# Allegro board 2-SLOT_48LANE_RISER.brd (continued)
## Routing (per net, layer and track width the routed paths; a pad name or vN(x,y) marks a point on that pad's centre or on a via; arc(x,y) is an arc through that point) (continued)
85OHM_BOT_10INCH_DP: length 254
  BOTTOM w0.135: U45.1 -15.06,45.46 -15.06,43.23 -15.27,42.02 -15.02,41.66 -7.7,40.37 -7.55,40.15 -7.64,39.63 -7.85,39.48 -17.46,41.18 -17.9,40.88 -18.03,40.1 -17.76,39.7 -7.93,37.97 -7.73,37.69 -7.81,37.23 -8.03,37.07 -17.33,38.71 -17.72,38.45 -17.88,37.62 -17.61,37.23 -8.13,35.56 -7.99,35.35 -8.07,34.87 -8.34,34.69 -17.4,36.28 -17.75,36.04 -17.9,35.21 -17.61,34.79 -8.1,33.12 -7.97,32.93 -8.07,32.36 -8.25,32.23 -17.39,33.84 -17.77,33.58 -17.92,32.72 -17.67,32.36 -8.15,30.68 -8.01,30.48 -8.1,29.93 -8.3,29.8 -17.46,31.41 -17.85,31.14 -18,30.3 -17.73,29.93 -8.18,28.25 -8.05,28.05 -8.15,27.48 -8.32,27.36 -17.33,28.95 -17.7,28.69 -17.72,28.57 -17.84,27.87 -17.56,27.48 -8.41,25.84 -8.3,25.69 -8.4,25.12 -8.61,24.97 -17.45,26.53 -17.85,26.21 -17.95,25.43 -17.67,25.03 -8.32,23.39 -8.21,23.23 -8.32,22.64 -8.51,22.51 -17.52,24.1 -17.9,23.84 -17.92,23.71 -18.03,23.05 -17.73,22.62 -8.63,21.02 -8.48,20.73 -8.57,20.26 -8.78,20.12 -17.17,21.6 -17.56,21.33 -17.7,20.51 -17.42,20.11 -8.72,18.57 -8.57,18.36 -8.67,17.8 -8.84,17.68 -17.33,19.18 -17.71,18.91 -17.86,18.07 -17.6,17.7 -8.67,16.12 -8.57,15.98 -8.68,15.34 -8.83,15.24 -17.08,16.7 -17.51,16.4 -17.64,15.67 -17.32,15.21 -10.17,13.95 -10.05,13.78 -10.16,13.14 -10.29,13.06 -13.48,13.62 -14.35,13.46 -14.94,12.62 -14.94,9.77 U43.2
85OHM_L2_5INCH_DN: length 127
  TOP w0.135: U29.2 -7.39,257.76 -7.39,258.17 v2(-7.16,258.4) ; U25.1 -7.39,279.02 -7.39,278.61 v2(-7.16,278.38)
  IN2 w0.145: v2(-7.16,278.38) -7.4,278.14 -7.4,276.39 -6.9,275.67 -5.04,275.34 -4.69,274.85 -4.8,274.25 -5.3,273.9 -12.66,275.2 -12.82,275.08 -12.93,274.47 -12.81,274.31 -5.45,273.01 -5.1,272.51 -5.21,271.91 -5.71,271.56 -13.2,272.88 -13.37,272.77 -13.48,272.16 -13.36,271.99 -5.87,270.67 -5.52,270.17 -5.62,269.57 -6.12,269.22 -13.71,270.56 -13.88,270.45 -13.99,269.84 -13.87,269.67 -6.28,268.33 -5.93,267.83 -6.04,267.23 -6.53,266.89 -14.58,268.31 -14.75,268.19 -14.85,267.58 -14.74,267.41 -6.69,265.99 -6.34,265.5 -6.45,264.9 -6.95,264.55 -16.13,266.17 -16.44,265.95 -16.51,265.58 -16.29,265.28 -7.1,263.66 -6.75,263.16 -6.86,262.56 -7.36,262.21 -16.55,263.83 -16.85,263.62 -16.92,263.25 -16.7,262.94 -7.52,261.32 -7.17,260.82 -7.4,259.49 -7.4,258.64 v2(-7.16,258.4)
85OHM_L2_5INCH_DP: length 127
  TOP w0.135: v2(-7.92,258.4) -7.69,258.17 -7.69,257.77 U29.1 ; v2(-7.92,278.38) -7.69,278.62 -7.69,279.02 U25.2
  IN2 w0.145: v2(-7.92,258.4) -7.68,258.64 -7.68,259.51 -7.46,260.75 -7.68,261.06 -16.87,262.68 -17.21,263.18 -17.11,263.78 -16.61,264.13 -7.42,262.51 -7.12,262.72 -7.05,263.09 -7.27,263.4 -16.45,265.02 -16.8,265.52 -16.7,266.12 -16.2,266.46 -7.01,264.84 -6.7,265.06 -6.64,265.43 -6.85,265.74 -14.9,267.16 -15.15,267.51 -15,268.35 -14.64,268.6 -6.6,267.18 -6.29,267.4 -6.23,267.77 -6.44,268.08 -14.03,269.41 -14.28,269.77 -14.13,270.61 -13.78,270.86 -6.19,269.52 -5.88,269.73 -5.81,270.11 -6.03,270.41 -13.53,271.74 -13.78,272.09 -13.63,272.93 -13.27,273.18 -5.77,271.86 -5.47,272.07 -5.4,272.44 -5.62,272.75 -12.98,274.05 -13.23,274.41 -13.08,275.24 -12.72,275.49 -5.36,274.2 -5.05,274.41 -4.99,274.78 -5.2,275.09 -7.04,275.41 -7.06,275.42 -7.68,276.3 -7.68,278.14 v2(-7.92,278.38)
85OHM_L2_10INCH_DN: length 254
  TOP w0.135: v2(-8.18,72.01) -7.95,71.78 -7.95,71.37 U33.1 ; v2(-8.18,106.43) -7.94,106.66 -7.94,107.06 U37.2
  IN2 w0.145: v2(-8.18,106.43) -7.94,106.18 -7.94,104.78 -7.79,103.98 -6.64,102.33 -6.77,101.6 -6.93,101.48 -12.68,102.49 -13.16,102.15 -13.27,101.53 -12.94,101.05 -4.14,99.5 -4.02,99.33 -4.13,98.72 -4.3,98.6 -13.09,100.15 -13.59,99.8 -13.7,99.21 -13.35,98.71 -4.56,97.16 -4.45,96.99 -4.55,96.38 -4.72,96.27 -13.51,97.82 -14,97.47 -14.11,96.87 -13.76,96.37 -4.86,94.8 -4.75,94.64 -4.85,94.03 -5.02,93.91 -13.92,95.48 -14.41,95.13 -14.52,94.53 -14.17,94.03 -5.17,92.45 -5.06,92.28 -5.16,91.67 -5.33,91.55 -14.33,93.14 -14.83,92.79 -14.93,92.19 -14.58,91.7 -4.58,89.93 -4.46,89.76 -4.57,89.16 -4.73,89.04 -14.74,90.8 -15.24,90.45 -15.34,89.86 -15,89.36 -4.97,87.59 -4.82,87.38 -4.92,86.81 -5.09,86.69 -15.15,88.46 -15.65,88.12 -15.76,87.52 -15.41,87.02 -5.29,85.24 -5.12,85 -5.22,84.45 -5.39,84.33 -15.57,86.13 -16.06,85.78 -16.17,85.18 -15.82,84.68 -5.6,82.88 -5.44,82.65 -5.53,82.17 -5.78,81.99 -15.98,83.79 -16.48,83.44 -16.58,82.84 -16.23,82.34 -5.8,80.51 -5.65,80.29 -5.75,79.74 -5.94,79.61 -16.39,81.45 -16.89,81.1 -16.99,80.5 -16.65,80.01 -6.44,78.21 -6.27,77.96 -6.35,77.52 -6.63,77.32 -16.8,79.11 -17.3,78.76 -17.41,78.17 -17.06,77.67 -7.72,76.02 -7.48,75.68 -7.92,73.19 -7.92,72.26 v2(-8.18,72.01)
85OHM_L2_10INCH_DP: length 254
  TOP w0.135: U33.2 -7.65,71.37 -7.65,71.78 v2(-7.42,72.01) ; U37.1 -7.64,107.06 -7.64,106.65 v2(-7.42,106.43)
  IN2 w0.145: v2(-7.42,72.01) -7.64,72.24 -7.64,73.17 -7.19,75.75 -7.56,76.28 -16.9,77.92 -17.11,78.23 -17.05,78.6 -16.74,78.82 -6.56,77.02 -6.09,77.35 -5.97,78.03 -6.28,78.46 -16.48,80.26 -16.7,80.57 -16.63,80.94 -16.33,81.16 -5.88,79.31 -5.49,79.58 -5.36,80.36 -5.64,80.76 -16.07,82.6 -16.29,82.91 -16.22,83.28 -15.91,83.49 -5.71,81.69 -5.27,82 -5.15,82.72 -5.44,83.14 -15.66,84.94 -15.87,85.25 -15.81,85.62 -15.5,85.83 -5.32,84.04 -4.97,84.29 -4.83,85.06 -5.13,85.49 -15.25,87.28 -15.46,87.58 -15.4,87.95 -15.09,88.17 -5.03,86.39 -4.67,86.64 -4.53,87.45 -4.81,87.85 -14.83,89.61 -15.05,89.92 -14.98,90.29 -14.68,90.51 -4.67,88.74 -4.31,88.99 -4.16,89.82 -4.29,90 -4.42,90.19 -14.42,91.95 -14.64,92.26 -14.57,92.63 -14.26,92.84 -5.27,91.26 -4.91,91.51 -4.76,92.35 -5.01,92.7 -14.01,94.29 -14.23,94.6 -14.16,94.97 -13.85,95.18 -4.96,93.61 -4.6,93.86 -4.45,94.7 -4.7,95.06 -13.6,96.63 -13.81,96.93 -13.75,97.3 -13.44,97.52 -4.66,95.97 -4.3,96.22 -4.15,97.06 -4.4,97.42 -13.18,98.96 -13.4,99.27 -13.34,99.64 -13.03,99.86 -4.23,98.31 -3.88,98.56 -3.73,99.39 -3.79,99.49 -3.98,99.75 -12.77,101.3 -12.98,101.6 -12.91,101.99 -12.62,102.2 -6.87,101.18 -6.51,101.43 -6.34,102.39 -7.53,104.09 -7.66,104.81 -7.66,106.18 v2(-7.42,106.43)
85OHM_TOP_5INCH_DN: length 127
  TOP w0.135: U26.2 -14.93,340.62 -14.93,338.38 -15.14,337.17 -14.89,336.81 -7.57,335.52 -7.42,335.3 -7.51,334.78 -7.72,334.63 -17.34,336.33 -17.77,336.02 -17.91,335.24 -17.77,335.05 -17.63,334.85 -7.63,333.09 -7.4,332.76 -7.48,332.3 -7.66,332.18 -17.21,333.86 -17.6,333.6 -17.75,332.76 -17.48,332.38 -7.91,330.69 -7.7,330.39 -7.79,329.89 -7.93,329.79 -17.05,331.39 -17.43,331.13 -17.58,330.31 -17.29,329.91 -8.27,328.32 -8.09,328.05 -8.18,327.52 -8.33,327.41 -17.2,328.98 -17.59,328.71 -17.74,327.87 -17.47,327.5 -8.54,325.92 -8.44,325.77 -8.55,325.14 -8.7,325.04 -16.96,326.49 -17.38,326.2 -17.51,325.47 -17.19,325.01 -10.04,323.74 -9.92,323.57 -10.04,322.94 -10.16,322.85 -13.35,323.42 -14.22,323.26 -14.81,322.42 -14.81,319.58 U5.1
85OHM_TOP_5INCH_DP: length 127
  TOP w0.135: U5.2 -14.51,319.58 -14.51,322.33 -14.04,322.98 -13.35,323.11 -10.09,322.53 -9.86,322.69 -9.76,322.76 -9.6,323.65 -9.87,324.02 -17.01,325.28 -17.19,325.54 -17.1,326.02 -16.89,326.17 -8.63,324.72 -8.27,324.96 -8.12,325.85 -8.37,326.2 -17.3,327.78 -17.41,327.94 -17.31,328.53 -17.13,328.66 -8.26,327.09 -7.9,327.34 -7.77,328.13 -8.09,328.59 -17.12,330.19 -17.25,330.38 -17.2,330.66 -17.15,330.95 -16.98,331.07 -7.86,329.46 -7.69,329.59 -7.68,329.59 -7.51,329.71 -7.38,330.46 -7.56,330.72 -7.74,330.97 -17.31,332.66 -17.43,332.83 -17.37,333.13 -17.32,333.42 -17.14,333.54 -7.58,331.86 -7.2,332.12 -7.08,332.83 -7.45,333.36 -17.45,335.13 -17.59,335.32 -17.49,335.85 -17.27,336 -7.65,334.31 -7.23,334.61 -7.1,335.37 -7.39,335.79 -14.71,337.09 -14.82,337.24 -14.63,338.35 -14.63,340.62 U26.1
85OHM_TOP_10INCH_DN: length 254
  TOP w0.135: U34.2 -14.93,164.85 -14.93,162.61 -15.14,161.4 -14.89,161.04 -7.57,159.75 -7.42,159.53 -7.51,159.01 -7.72,158.86 -17.34,160.56 -17.77,160.26 -17.91,159.48 -17.63,159.08 -7.8,157.35 -7.6,157.07 -7.68,156.61 -7.9,156.45 -17.21,158.09 -17.6,157.83 -17.75,157 -17.48,156.61 -8.01,154.94 -7.86,154.73 -7.95,154.25 -8.21,154.07 -17.27,155.66 -17.63,155.42 -17.77,154.59 -17.48,154.17 -7.98,152.5 -7.84,152.31 -7.94,151.74 -8.12,151.61 -17.27,153.22 -17.64,152.96 -17.79,152.1 -17.54,151.74 -8.02,150.06 -7.88,149.86 -7.98,149.31 -8.17,149.18 -17.33,150.79 -17.72,150.52 -17.87,149.68 -17.61,149.31 -8.06,147.63 -7.92,147.43 -8.02,146.86 -8.2,146.74 -17.2,148.33 -17.57,148.07 -17.59,147.95 -17.71,147.25 -17.44,146.86 -8.28,145.22 -8.17,145.07 -8.27,144.5 -8.49,144.35 -17.32,145.91 -17.72,145.59 -17.83,144.81 -17.54,144.41 -8.2,142.77 -8.09,142.61 -8.19,142.02 -8.38,141.89 -17.39,143.48 -17.77,143.22 -17.79,143.09 -17.91,142.43 -17.6,142 -8.5,140.4 -8.36,140.11 -8.44,139.64 -8.65,139.5 -17.05,140.98 -17.43,140.71 -17.58,139.89 -17.29,139.49 -8.59,137.95 -8.44,137.74 -8.54,137.18 -8.71,137.06 -17.2,138.56 -17.59,138.29 -17.74,137.45 -17.47,137.08 -8.54,135.5 -8.44,135.36 -8.55,134.72 -8.7,134.62 -16.96,136.08 -17.38,135.78 -17.51,135.05 -17.19,134.59 -10.04,133.33 -9.92,133.16 -10.04,132.52 -10.16,132.44 -13.35,133 -14.22,132.84 -14.81,132 -14.81,129.16 U30.1
85OHM_TOP_10INCH_DP: length 254
  TOP w0.135: U34.1 -14.63,164.85 -14.63,162.58 -14.82,161.47 -14.71,161.32 -7.39,160.03 -7.1,159.6 -7.23,158.84 -7.65,158.54 -17.27,160.24 -17.49,160.08 -17.59,159.55 -17.45,159.36 -7.62,157.63 -7.28,157.14 -7.41,156.43 -7.83,156.13 -17.14,157.77 -17.32,157.65 -17.43,157.07 -17.31,156.89 -7.83,155.22 -7.54,154.81 -7.67,154.07 -8.14,153.74 -17.2,155.34 -17.35,155.24 -17.45,154.66 -17.3,154.45 -7.8,152.77 -7.52,152.38 -7.66,151.56 -8.05,151.29 -17.19,152.9 -17.36,152.78 -17.47,152.17 -17.37,152.02 -7.84,150.34 -7.56,149.93 -7.7,149.13 -8.1,148.85 -17.26,150.47 -17.45,150.34 -17.55,149.76 -17.43,149.59 -7.88,147.9 -7.6,147.5 -7.75,146.68 -8.13,146.42 -17.13,148.01 -17.29,147.89 -17.39,147.32 -17.26,147.13 -8.11,145.5 -7.85,145.14 -7.99,144.32 -8.42,144.03 -17.24,145.58 -17.44,145.42 -17.51,144.89 -17.37,144.69 -8.02,143.05 -7.76,142.68 -7.91,141.84 -8.31,141.57 -17.32,143.15 -17.49,143.04 -17.58,142.51 -17.43,142.28 -8.29,140.67 -8.04,140.16 -8.16,139.47 -8.58,139.17 -16.98,140.65 -17.15,140.53 -17.25,139.96 -17.12,139.77 -8.42,138.23 -8.12,137.81 -8.26,137.01 -8.64,136.74 -17.13,138.24 -17.31,138.11 -17.41,137.52 -17.3,137.36 -8.37,135.78 -8.12,135.43 -8.27,134.54 -8.63,134.3 -16.89,135.75 -17.1,135.6 -17.19,135.12 -17.01,134.87 -9.87,133.6 -9.6,133.23 -9.76,132.35 -9.86,132.27 -9.86,132.27 -10.09,132.11 -13.35,132.69 -14.04,132.57 -14.51,131.91 -14.51,129.16 U30.2
AT24C64_A0: length 4.7
  TOP w0.114: R281.2 v2(315.16,44.78) R282.1 315.65,43.61 315.65,42.11 315.16,41.63 U7.1
AT24C64_A1: length 4.7
  TOP w0.114: 313.89,41.12 313.89,41.88 314.34,42.32 314.34,43.64 R284.1 v2(313.89,44.78) R283.2
AT24C64_A2: length 4.7
  TOP w0.114: R285.2 v2(312.62,44.78) R286.1 313.13,43.58 313.13,42.29 312.62,41.78 U7.3
AT24C64_WP: length 4.5
  TOP w0.114: R293.2 R294.1 314.56,33.53 314.56,34.52 v2(314.53,34.54) 313.89,35.18 313.89,35.84
CLK_100M_CPU1_PE_FG_DN: length 77.7
  TOP w0.135: v2(282.22,11.99) 282.53,11.68 282.53,10.46 280.87,8.81 280.87,6.83 281.17,6.53 281.17,6.15 280.83,5.8 J5.A14 ; 301.31,56.32 U9.7 301.31,55.38 302.9,53.8 v8(302.9,50.09) 302.9,49.02 v2(303.15,48.77)
  IN2 w0.145: v2(303.15,48.77) 303.13,48.77 302.9,48.54 302.9,45.91 303.4,45.4 303.4,39.62 304.65,38.38 304.65,32.72 304.12,32.18 304.12,30.99 304.42,30.68 304.42,29.49 304.65,29.26 304.65,22.63 303.35,21.34 303.35,14.99 298.38,10.01 283.87,10.01 282.54,11.34 282.54,11.67 v2(282.22,11.99)
CLK_100M_CPU1_PE_FG_DP: length 77.6
  TOP w0.135: v2(302.34,48.77) 302.39,48.77 302.59,48.97 v8(302.59,51.64) 302.59,53.67 301.01,55.26 301.01,55.64 300.91,55.73 U9.6 300.91,56.32 ; J5.A13 281.83,5.8 281.48,6.15 281.48,6.66 281.18,6.96 281.18,8.69 282.83,10.34 282.83,11.79 v2(283.03,11.99)
  IN2 w0.145: v2(283.03,11.99) 282.82,11.77 282.82,11.46 283.99,10.29 285.15,10.29 285.26,10.4 285.89,10.4 286,10.29 289.36,10.29 289.48,10.4 290.1,10.4 290.22,10.29 291.08,10.29 291.19,10.4 291.82,10.4 291.93,10.29 298.26,10.29 298.76,10.79 298.76,10.95 299.2,11.39 299.36,11.39 300.72,12.75 300.72,12.91 301.17,13.36 301.33,13.36 301.94,13.96 301.94,14.12 302.38,14.57 302.54,14.57 303.07,15.1 303.07,21.45 304.37,22.75 304.37,29.14 304.14,29.37 304.14,30.57 303.84,30.87 303.84,32.3 304.37,32.83 304.37,34.3 304.26,34.41 304.26,35.04 304.37,35.15 304.37,36.01 304.26,36.12 304.26,36.75 304.37,36.87 304.37,38.26 303.13,39.51 303.13,39.93 303.02,40.03 303.02,40.69 303.13,40.79 303.13,45.29 302.62,45.8 302.62,48.51 302.36,48.77 v2(302.34,48.77)
CLK_100M_PEX8796_DN: length 3.8
  TOP w0.135: 301.31,61.07 U9.24 301.31,61.59 301.36,61.64 301.36,62.39 301.95,62.98 301.95,64.12 R127.1
CLK_100M_PEX8796_DP: length 3.8
  TOP w0.135: 301.71,61.07 U9.23 301.71,61.58 301.66,61.63 301.66,62.26 302.26,62.86 302.26,64.17 R126.1
CLK_100M_PEX8796_R_DN: length 236.6
  TOP w0.135: R127.2 301.96,65.69 301.96,66.73 301.68,67.01 301.53,67.01 301.09,67.44 301.09,67.59 300.81,67.87 297.92,67.87 297.18,67.13 v8(297.18,66.8) 297.18,64.44 295.31,62.57 295.31,62.47 295.31,62.37 295,62.06 294.9,62.06 294.8,62.06 292.3,59.56 292.3,59.46 292.3,59.46 292.3,59.36 291.99,59.05 291.89,59.05 291.89,59.05 291.79,59.05 289.63,56.89 289.63,56.78 289.63,56.68 289.32,56.37 289.22,56.37 289.21,56.37 289.11,56.37 285.24,52.5 285.24,52.27 284.86,51.89 284.63,51.89 284.25,51.51 284.25,51.28 283.87,50.9 283.64,50.9 281.76,49.02 281.76,48.88 281.76,48.88 281.76,48.74 281.45,48.43 281.31,48.43 281.17,48.43 279.29,46.55 279.29,46.45 279.29,46.45 279.29,46.35 278.98,46.03 278.88,46.03 278.88,46.04 278.78,46.04 277.95,45.21 277.95,44.2 278.11,44.04 278.11,43.5 277.95,43.35 277.95,39.12 276.96,38.13 276.96,34.82 275.95,33.81 275.95,30.56 v2(276.2,30.3)
  IN2 w0.145: v5(125.69,77.96) 125.69,78.07 125.54,78.22 125.33,78.22 125.08,77.97 125.08,76.5 125.2,76.38 125.2,75.71 125.08,75.59 125.08,75.01 125.2,74.89 125.2,74.31 125.08,74.19 125.08,72.64 145.65,52.07 181.05,52.07 183.95,49.17 204.27,49.17 208.84,44.6 208.84,34.84 212.69,30.99 272.73,30.99 273.7,31.95 275.3,31.95 275.92,31.33 275.92,30.56 276.18,30.3 v2(276.2,30.3)
  BOTTOM w0.135: U1.W2 v5(125.69,77.96)
CLK_100M_PEX8796_R_DP: length 236.7
  TOP w0.135: R126.2 302.26,65.63 302.26,66.85 300.94,68.17 297.79,68.17 296.88,67.26 v8(296.88,65.07) 296.88,64.57 277.65,45.34 277.65,39.24 276.66,38.25 276.66,34.95 275.64,33.93 275.64,30.56 v2(275.39,30.3)
  IN2 w0.145: v5(125.69,78.76) 125.69,78.62 125.57,78.5 125.21,78.5 124.8,78.09 124.8,72.52 145.53,51.79 180.94,51.79 183.83,48.9 204.15,48.9 208.56,44.49 208.56,34.72 212.57,30.71 272.85,30.71 273.81,31.67 275.19,31.67 275.64,31.22 275.64,30.53 275.41,30.3 v2(275.39,30.3)
  BOTTOM w0.135: U1.W3 v5(125.69,78.76)
CLK_100M_SLOT1_DN: length 3.8
  TOP w0.135: 303.09,58.5 U9.15 303.61,58.5 303.65,58.45 304.49,58.45 305.08,57.86 306.13,57.86 R125.1
CLK_100M_SLOT1_DP: length 3.8
  TOP w0.135: 303.09,58.1 U9.14 303.6,58.1 303.65,58.15 304.36,58.15 304.96,57.55 306.18,57.55 R124.1
CLK_100M_SLOT1_R_DN: length 59.4
  TOP w0.135: R125.2 307.62,57.94 308.69,57.94 310.77,55.86 310.77,54.1 v2(311,53.87)
  BOTTOM w0.135: J1.A14 281.2,34 281.38,34.06 281.51,33.99 281.64,33.86 281.64,32.39 283.03,30.99 296.42,30.99 299.7,34.26 309.55,34.26 310.8,35.51 310.8,53.7 310.97,53.87 v2(311,53.87)
CLK_100M_SLOT1_R_DP: length 59.4
  TOP w0.135: v2(310.19,53.87) 310.47,54.15 310.47,55.73 308.57,57.63 307.72,57.63 R124.2
  BOTTOM w0.135: J1.A13 281.46,34.51 281.52,34.33 281.69,34.25 281.94,33.99 281.94,32.51 282.23,32.23 282.44,32.23 282.73,31.94 282.73,31.73 283.16,31.29 285.15,31.29 285.33,31.47 285.77,31.47 285.95,31.29 289.65,31.29 289.83,31.47 290.27,31.47 290.45,31.29 294.62,31.29 294.8,31.47 295.24,31.47 295.42,31.29 296.29,31.29 298.09,33.09 298.09,33.2 298.09,33.3 298.41,33.61 298.51,33.61 298.61,33.61 299.57,34.57 301.04,34.57 301.2,34.72 301.69,34.72 301.84,34.57 309.43,34.57 310.49,35.64 310.49,48.59 310.29,48.79 310.29,49.23 310.49,49.43 310.49,53.59 310.21,53.87 v2(310.19,53.87)
CLK_100M_SLOT2_DN: length 4
  TOP w0.135: 300.11,61.07 U9.27 300.11,61.54 300.16,61.58 300.16,62.06 299.13,63.08 299.13,64.14 R123.1
CLK_100M_SLOT2_DP: length 4
  TOP w0.135: R122.1 299.44,64.14 299.44,63.21 300.46,62.18 300.46,61.61 300.51,61.57 U9.26 300.51,61.07
CLK_100M_SLOT2_R_DN: length 27.4
  TOP w0.135: R123.2 299.13,65.66 299.13,66.58 v2(298.86,66.85)
  BOTTOM w0.135: J2.A14 281.2,74.64 281.38,74.7 281.51,74.63 281.64,74.5 281.64,73.02 282.64,72.02 282.64,69.23 284.71,67.16 288.64,67.16 288.82,66.98 289.26,66.98 289.44,67.16 292.5,67.16 292.68,66.98 293.12,66.98 293.29,67.16 296.65,67.16 297.18,67.69 298.81,67.69 299.09,67.41 299.09,67.08 v2(298.86,66.85)
CLK_100M_SLOT2_R_DP: length 27.5
  TOP w0.135: v2(299.67,66.86) 299.44,66.62 299.44,65.66 R122.2
  BOTTOM w0.135: v2(299.67,66.86) 299.39,67.14 299.39,67.54 298.93,68 297.06,68 296.52,67.46 284.84,67.46 282.95,69.35 282.95,72.14 281.94,73.15 281.94,74.63 281.69,74.89 281.52,74.97 281.46,75.15 J2.A13
CLK_BUF_CKPWRGD: length 6.8
  TOP w0.114: 299.71,56.32 U9.3 299.71,55.66 299.31,55.26 299.31,53.6 v2(299.37,53.54) 299.31,53.49 R4.2 299.8,51.02 Q4.D
CLK_BUF_HIBW_BYPM_LOBW_N: length 4
  TOP w0.178: 298.79,54.94 298.79,55.14 299.31,55.67 U9.2 299.31,56.32
  TOP w0.254: 298.79,54.94 298.79,53.94 R2.1 R1.2
CPLD_PWRBRK_BUF_N: length 84.3
  TOP w0.114: U19.2 v2(283.54,85.72) ; U8.4 281.42,18.86 R154.1 281.49,19.34 281.64,19.48 282.86,19.48 283.03,19.66 v1(283.03,22.12) 283.03,23.29 280.98,25.35 v2(280.98,25.73) ; v2(283.36,45.49) 283.08,45.21 U20.2
  IN2 w0.147: v2(280.98,25.73) 281.33,26.09 281.33,28.06 284.87,31.6 286.31,31.6 287.73,33.02 287.73,34.19 286.69,35.23 286.69,38.23 284.15,40.77 284.15,44.7 v2(283.36,45.49) 283.36,47.8 286.71,51.15 286.71,60.08 280.57,66.22 280.57,69.01 281.97,70.41 281.97,74.35 282.16,74.82 282.52,75.18 282.78,75.56 282.78,75.95 282.4,76.87 282.4,77.44 283.05,79.01 283.92,79.88 283.92,81.69 282.88,82.73 282.88,85.52 283.08,85.72 v2(283.54,85.72)
CPLD_PWRBRK_N: length 26.3
  TOP w0.114: U8.2 277.07,19.51 v2(277.06,19.51) ; R152.2 v2(263.7,10.82)
  IN2 w0.147: v2(277.06,19.51) 273.86,16.31 269.7,16.31 264.21,10.82 v2(263.7,10.82)
  BOTTOM w0.114: v2(263.7,10.82) 264.83,9.7 J5.B30
CPLD_SLOT1_PWRBRK_N: length 4.2
  TOP w0.114: R221.1 R216.1 R142.2 285.14,43.45 285.39,43.71 285.39,43.76 285.4,43.76 v2(285.4,44.07) 285.4,44.32 285.16,44.56 U20.4
CPLD_SLOT1_PWRBRK_R1_N: length 3.3
  TOP w0.114: J1.B12 283.8,40.72 R216.2
CPLD_SLOT1_PWRBRK_R2_N: length 19.2
  TOP w0.114: R221.2 v2(278.74,42.65)
  IN1 w0.147: v2(278.74,42.65) 267.73,42.65 J1.B30
CPLD_SLOT2_PWRBRK_N: length 3.8
  TOP w0.114: R214.1 v2(283.8,84.71) 283.8,84.84 284.03,85.08 U19.4 ; R214.1 R143.2 ; R214.1 R215.1
CPLD_SLOT2_PWRBRK_R1_N: length 3.2
  TOP w0.114: J2.B12 283.8,81.36 R214.2
CPLD_SLOT2_PWRBRK_R2_N: length 19.1
  TOP w0.114: R215.2 267.6,83.17 J2.B30
DC_PEX8747_AA18: length 0.6
  BOTTOM w0.114: U1.AA18 v5(124.09,91.56)
DC_PEX8747_AA21: length 0.6
  BOTTOM w0.114: U1.AA21 v5(124.89,93.96)
DC_PEX8747_B9: length 0.6
  BOTTOM w0.114: U1.B9 v5(139.29,83.56)
DC_PEX8747_F13: length 0.6
  BOTTOM w0.114: U1.F13 v5(136.89,87.56)
DC_PEX8747_F20: length 0.6
  BOTTOM w0.114: U1.F20 v5(136.89,93.16)
DC_PEX8747_F21: length 0.6
  BOTTOM w0.114: U1.F21 136.49,93.56 v5(136.09,93.96)
DC_PEX8747_N22: length 0.6
  BOTTOM w0.114: U1.N22 v5(130.49,94.76)
DC_PEX8747_Y16: length 0.6
  BOTTOM w0.114: U1.Y16 v5(124.89,89.96)
DC_PEX8747_Y20: length 0.6
  BOTTOM w0.114: U1.Y20 v5(124.89,93.16)
EMC1412_ADDR: length 2.7
  BOTTOM w0.114: R302.2 306.53,81.15 v4(306.24,80.86) 305.8,80.42 U4.4
EMC1412_ALERT: length 4
  BOTTOM w0.114: R301.2 v4(311.99,80.14) 311.92,80.06 311.92,79.19 311.79,79.07 U4.6
EMC1413_ADDR: length 4.7
  TOP w0.114: U10.7 204.9,80.21 v2(206.59,78.52) 206.91,78.21 R137.2
EMC1413_ALERT_N: length 4.4
  TOP w0.114: R141.2 206.99,79.91 v2(206.55,79.91) 205.74,79.91 204.94,80.71 U10.8
I2C_ADDR0: length 7.8
  TOP w0.102: v5(136.89,80.36) 136.5,79.97 135.96,79.97 135.71,79.72 135.71,79.32 135.33,78.95 135.33,76.71 v6(135.56,76.48)
  TOP w0.114: v6(135.56,76.48) 135.33,76.25 135.33,75.88 135.21,75.75 R108.1 R94.2
  BOTTOM w0.114: U1.F5 v5(136.89,80.36)
I2C_MUX_ADD_A0: length 6.7
  TOP w0.114: U2.1 308.04,41.16 308.54,41.66 v2(309.32,41.66) 309.45,41.78 309.45,43.69 309.72,43.96 R84.1 R83.2
I2C_MUX_ADD_A1: length 5.9
  TOP w0.114: R81.2 v2(308.81,44.73) R82.1 308.23,43.38 308.23,41.88 307.39,41.04 U2.2
I2C_MUX_ADD_A2: length 5.7
  TOP w0.114: U2.21 306.09,32.21 v2(306.2,32.11) 306.45,31.85 306.45,31.07 R80.1 R79.2
I2C_MUX_RST_N: length 3.4
  TOP w0.114: R78.2 307.67,42.62 v2(307.37,42.32) 307.34,42.32 306.74,41.72 U2.3
I2C_PCA9548_2N7002_G2_SCL: length 2.1
  TOP w0.254: R160.2 v2(315.7,28.7) 316.24,28.16 Q19.G
I2C_PCA9548_2N7002_G2_SDA: length 1.9
  TOP w0.254: R163.2 v2(311.84,28.7) 312.05,28.49 Q22.G
I2C_PCA9548_2N7002_G_SCL: length 2.2
  TOP w0.114: R161.2 296.26,24.28 v2(296.5,24.51) 297.23,24.51 Q20.G
I2C_PCA9548_2N7002_G_SDA: length 2.2
  TOP w0.114: R191.2 290.17,24.28 v2(290.4,24.51) 291.14,24.51 Q23.G
I2C_PCA9548_SC1_SLOT2_R_SCL: length 3.2
  TOP w0.114: R22.1 303.61,42.06 v2(304.1,41.57) 304.14,41.53 U2.7
I2C_PCA9548_SC1_SLOT2_SCL: length 35.7
  TOP w0.114: R22.2 304.24,44.6 v2(304.24,44.7) R98.2 ; v2(292.22,65.11) Q15.D 291.78,67.24 R226.1
  BOTTOM w0.114: v2(292.22,65.11) 292.1,64.99 292.1,49.45 294.69,46.86 300.64,46.86 302.3,45.2 302.33,45.2 302.82,44.7 v2(304.24,44.7)
I2C_PCA9548_SC3_SLOT1_R_SCL: length 4.6
  TOP w0.114: U2.11 301.54,41.01 301.25,41.3 300.05,41.3 v2(299.82,41.53) 299.67,41.68 R26.1
I2C_PCA9548_SC3_SLOT1_SCL: length 30.1
  TOP w0.114: R102.2 298.4,44.68 v2(298.4,44.32) 298.76,43.96 R26.2 ; Q21.D 294.32,26.8 294.69,27.16 R228.1 295.23,26.98 295.55,26.65 295.55,26.43 295.56,26.43 v2(295.56,26.26)
  IN2 w0.147: v2(298.4,44.32) 298.4,43.64 298.23,43.47 297.43,43.47 297.28,43.32 297.28,43.03 297.43,42.88 298.25,42.88 298.4,42.73 298.4,42.52 297.52,41.64 297.52,32.76 298.53,31.75 298.53,27.56 298.15,27.18 296.47,27.18 v2(295.56,26.26)
I2C_PCA9548_SC5_3V3_PE_SCL: length 336.7
  TOP w0.114: Q20.S v2(297.68,21.1) ; v2(193.27,82.83) 194.41,83.97 194.41,99.96 188.37,106.01 188.37,113.08 189.06,113.78 CON1.2 191.97,113.78 192.89,112.85 196.85,112.85 v2(203.28,106.43) ; U12.7 105.61,45.11 105.95,45.44 107.4,45.44 R234.2 R194.2 107.81,44.05 108.72,44.05 v2(108.74,44.03)
  IN1 w0.147: v2(193.27,82.83) 160.57,82.83 122.11,44.37 109.22,44.37 108.88,44.03 v2(108.74,44.03)
  IN2 w0.147: v2(203.28,106.43) 206.83,102.87 265.38,102.87 277.45,90.81 284.43,90.81 289.89,85.34 289.89,82.68 291.8,80.77 291.8,79.88 292.94,78.74 292.94,75.69 291.92,74.68 291.92,73.08 290.42,71.57 290.42,67.6 289.73,66.91 289.73,47.78 292.51,45 297.35,45 298.17,45.82 301.6,45.82 301.96,45.47 301.96,42.04 301.58,41.66 301.58,39.98 301.96,39.6 301.96,37.19 301.63,36.86 301.63,32.59 302.21,32 302.21,29.72 302.34,29.59 302.34,22.99 300.45,21.1 v2(297.68,21.1)
I2C_PCA9548_SC5_P1V8_SCL: length 191.6
  TOP w0.114: v5(136.89,81.96) 137.3,81.55 139.59,81.55 140.21,80.92 140.21,80.75 140.72,80.24 142.37,80.24 142.9,80.77 173.75,80.77 203.91,50.61 203.91,45.47 v2(204.45,44.93) ; U12.2 105.61,47.22 v2(106.05,46.79)
  IN2 w0.147: v2(106.05,46.79) 106.1,46.74 108.29,46.74 109.56,45.47 130.13,45.47 132.79,48.13 178.72,48.13 181.42,45.44 203.94,45.44 v2(204.45,44.93)
  BOTTOM w0.114: R277.2 105.36,47.47 v2(106.05,46.79) ; U1.F7 v5(136.89,81.96)
I2C_PCA9548_SC5_PE_R_SCL: length 3.6
  TOP w0.114: R28.1 301.83,32.77 v2(302.08,33.02) 302.84,33.78 U2.16
I2C_PCA9548_SC5_PE_SCL: length 226.5
  TOP w0.114: v2(109.97,46.23) 109.61,45.87 R234.1 ; R28.2 301.83,30.56 v2(301.17,29.89) R104.2 302.34,28.72 302.34,27.05 299.88,24.6 Q20.D
  IN2 w0.147: v2(109.97,46.23) 130.38,46.23 132.92,48.77 179.27,48.77 182.2,45.85 204.65,45.85 205.39,45.11 205.39,32.82 217,21.2 277.49,21.2 v2(280.39,24.1)
  BOTTOM w0.114: v2(280.39,24.1) 280.87,23.62 290.37,23.62 294.41,27.66 296.52,27.66 297.35,28.49 298.44,28.49 298.78,28.83 300.1,28.83 v2(301.17,29.89)
I2C_PCA9548_SC6_3V3_CLK_R_SCL: length 7.7
  TOP w0.114: R90.2 v2(305.52,51.64) 305.26,51.89 304.25,51.89 303.9,52.24 303.9,54.17 302.63,55.45 302.47,55.45 302.11,55.8 U9.9 302.11,56.32
I2C_PCA9548_SC6_3V3_CLK_SCL: length 38.2
  TOP w0.114: Q19.S 314.34,28.45 314.55,28.66 R236.2 314.94,29.34 315.47,29.87 v2(315.47,30.36) 315.25,30.57 R193.2 ; R90.1 v2(315.62,49.97)
  BOTTOM w0.114: v2(315.62,49.97) 316.02,49.97 318.85,47.14 318.85,33.67 317.28,32.1 317.28,31.94 317.57,31.65 317.57,31.44 317.37,31.24 317.2,31.24 316.88,31.56 316.74,31.56 315.54,30.36 v2(315.47,30.36)
I2C_PCA9548_SC6_CLK_R_SCL: length 3.6
  TOP w0.114: R30.1 304.14,31.67 304.14,32.69 v2(303.71,33.12) 304.14,33.55 U2.18
I2C_PCA9548_SC6_CLK_SCL: length 205.7
  TOP w0.114: R106.2 303.86,29.74 v2(303.66,29.95) 303.86,30.15 R30.2 ; Q19.D 314.74,25.32 313.51,26.54 313.51,28.32 313.75,28.56 R236.1 313.26,29.83 313.26,30.99 312.37,31.88 v2(312.37,32) 312.62,32.26 R280.2 ; v2(313.66,77.47) 313.79,77.6 314.91,77.6 316.69,79.38 316.69,83.57 311.23,89.03 296.24,89.03 291.42,93.85 219.33,93.85 210.03,84.56 210.03,82.98 208.65,81.6 R183.1
  BOTTOM w0.114: R299.1 v2(313.66,77.47) 313.66,76.09 311.85,74.28 305.28,74.28 304.05,73.05 304.05,65.46 312.73,56.78 312.73,48.18 313.16,47.75 313.16,41.78 312.09,40.72 312.09,32.28 v2(312.37,32) 311.76,31.39 309.15,31.39 308.81,31.06 304.24,31.06 303.66,30.48 v2(303.66,29.95)
I2C_PCA9548_SC6_EMC1053_SCL: length 4.5
  TOP w0.114: R183.2 206.75,82.45 v2(206.12,82.45) 205.39,81.71 U10.10
I2C_PCA9548_SC6_EMC1412_SCL: length 3.8
  BOTTOM w0.114: U4.8 310.98,77.76 v4(311.61,77.14) 311.77,77.14 R299.2
I2C_PCA9548_SC6_FRU_SCL: length 2.2
  TOP w0.114: R280.1 v2(312.62,34.54) U7.6
I2C_PCA9548_SC7_ADC128_R_SCL: length 3.4
  TOP w0.114: R151.1 305.64,31.67 305.64,33.05 v2(305.44,33.25) U2.20
I2C_PCA9548_SC7_ADC128_SCL_R: length 1.9
  TOP w0.114: U3.10 R157.1
I2C_PCA9548_SC7_ADC128_SDA: length 47
  TOP w0.114: R185.2 v2(304.93,29.95) R150.2 ; R158.2 267.57,27.94 267.69,28.07 267.69,28.83 v2(267.92,29.06)
  BOTTOM w0.114: v2(304.93,29.95) 304.93,28.12 303.96,27.15 294.49,27.15 290.45,23.11 273.86,23.11 v2(267.92,29.06)
I2C_PCA9548_SD1_SLOT2_R_SDA: length 4.4
  TOP w0.114: R21.1 305.11,43.43 v2(304.5,43.43) 304.5,42.41 304.79,42.11 U2.6
I2C_PCA9548_SD1_SLOT2_SDA: length 40.4
  TOP w0.114: R97.2 v2(305.39,44.73) R21.2 ; R227.1 287.97,68.43 288.16,68.24 Q18.D 288.16,66.3 v2(288.7,65.76)
  BOTTOM w0.114: v2(288.7,65.76) 292.71,65.76 292.99,65.48 292.99,64.47 292.58,64.06 292.58,49.65 295.05,47.19 300.71,47.19 302.44,45.47 304.65,45.47 v2(305.39,44.73)
I2C_PCA9548_SD3_SLOT1_R_SDA: length 3.6
  TOP w0.114: R25.1 v2(300.81,42.34) 302.19,40.97 U2.10
I2C_PCA9548_SD3_SLOT1_SDA: length 37.7
  TOP w0.114: Q24.D 288.57,26.8 v2(289,26.37) 289.13,26.49 R233.1 ; R101.2 300.81,45.39 v2(300.08,44.65) 300.77,43.96 R25.2
  IN2 w0.147: v2(300.08,44.65) 300.08,43.69 297.87,41.48 297.87,32.92 299.29,31.5 299.29,29.06 299.54,28.8 299.54,27.18 297.77,25.4 289.49,25.4 289,25.88 v2(289,26.37)
I2C_PCA9548_SD5_3V3_PE_SDA: length 350.4
  TOP w0.114: v4(111.2,43.69) 111.2,47.62 110.21,48.62 R209.2 R235.2 106.01,45.88 105.57,45.88 104.96,45.27 U12.6 ; CON1.3 189.4,111.78 188.85,111.23 188.85,106.05 194.78,100.11 194.78,82.22 194.45,81.89 v2(193.58,81.89) ; v2(291.8,21.11) 291.59,21.32 Q23.S
  IN1 w0.147: v2(193.58,81.89) 160.12,81.89 121.92,43.69 v4(111.2,43.69)
  IN2 w0.147: v2(291.8,21.11) 285.73,15.04 276.61,15.04 270.31,8.74 246.31,8.74 234.57,20.47 200.06,20.47 173.92,46.61 133.3,46.61 130.63,43.94 111.46,43.94 v4(111.2,43.69)
I2C_PCA9548_SD5_P1V8_SDA: length 190.2
  TOP w0.114: v5(136.89,78.76) 137.29,78.36 141.78,78.36 143.62,80.19 173.51,80.19 203.4,50.29 203.4,45.95 202.97,45.52 v2(202.97,44.83) ; v2(104.73,46.86) 104.96,47.1 U12.3
  IN2 w0.147: v2(104.73,46.86) 105.74,45.85 108.57,45.85 109.46,44.96 130.25,44.96 132.92,47.62 178.51,47.62 181.03,45.11 181.25,45.11 181.27,45.09 202.71,45.09 v2(202.97,44.83)
  BOTTOM w0.114: R278.2 104.34,47.24 v2(104.73,46.86) ; U1.F2 136.49,78.36 v5(136.89,78.76)
I2C_PCA9548_SD5_PE_R_SDA: length 3.8
  TOP w0.114: U2.15 302.19,33.76 300.69,32.26 v2(300.69,32.08) R27.1
I2C_PCA9548_SD5_PE_SDA: length 229.5
  TOP w0.114: Q23.D 298.27,23.11 298.91,23.75 298.91,24.71 301.25,27.05 301.25,28.67 R103.2 300.69,29.62 v2(300.36,29.95) 300.69,30.28 R27.2 ; v2(109.13,47.37) 108.6,46.84 R235.1
  IN2 w0.147: v2(279.48,24.89) 276.14,21.55 217.5,21.55 205.85,33.21 205.85,45.22 204.58,46.48 182.57,46.48 179.77,49.28 132.79,49.28 131,47.48 109.24,47.48 v2(109.13,47.37)
  BOTTOM w0.114: v2(300.36,29.95) 299.75,29.34 298.71,29.34 298.3,28.93 296.6,28.93 296.36,29.17 295.16,29.17 291.51,25.52 283.1,25.52 282.48,24.89 v2(279.48,24.89)
I2C_PCA9548_SD6_3V3_CLK_R_SDA: length 6.8
  TOP w0.114: 301.71,56.32 U9.8 301.71,55.69 302.35,55.06 302.49,55.06 303.53,54.02 303.53,51.73 v2(303.87,51.39) R89.2
I2C_PCA9548_SD6_3V3_CLK_SDA: length 41.7
  TOP w0.114: R89.1 304.52,49.97 305.26,49.23 v2(314.48,49.23) ; R204.2 311.35,30.66 v2(310.9,30.2) 310.67,29.97 310.52,29.97 310.07,29.52 R237.2 310.07,28.53 310.15,28.45 Q22.S
  BOTTOM w0.114: v2(314.48,49.23) 315.93,49.23 318.47,46.69 318.47,33.91 315.88,31.32 315.42,31.32 313.95,29.84 311.25,29.84 v2(310.9,30.2)
I2C_PCA9548_SD6_CLK_R_SDA: length 3.4
  TOP w0.114: R29.1 302.85,31.93 v2(302.95,32.03) 302.95,33.17 303.49,33.72 U2.17
I2C_PCA9548_SD6_CLK_SDA: length 206.8
  TOP w0.114: v2(314.53,78.61) 315.42,79.5 315.42,82.55 309.32,88.65 295.86,88.65 291.8,92.71 219.13,92.71 210.44,84.02 210.44,81.84 209.06,80.46 R184.1 ; R29.2 v2(302.85,29.95) R105.2 ; Q22.D 311.1,28.32 310.87,28.56 R237.1 312.21,30.68 v2(312.35,30.68) 312.35,30.91 311.86,31.39 311.86,32.37 R279.2
  BOTTOM w0.114: R300.1 314.02,79.12 v2(314.53,78.61) 314.53,76.07 312.37,73.91 305.44,73.91 304.42,72.9 304.42,65.61 313.09,56.93 313.09,48.7 314.5,47.29 314.5,42.11 312.62,40.23 312.62,37.39 313.25,36.77 313.25,32.78 313.64,32.38 313.64,31.68 312.65,30.68 v2(312.35,30.68) 312.14,30.68 311.86,30.96 309.73,30.96 309.37,30.61 304.62,30.61 304.24,30.23 304.24,29.46 303.99,29.21 302.97,29.21 302.85,29.34 v2(302.85,29.95)
I2C_PCA9548_SD6_EMC1053_SDA: length 4.2
  TOP w0.114: R184.2 206.85,81.21 v2(206.45,81.21) U10.9
I2C_PCA9548_SD6_EMC1412_SDA: length 3.4
  BOTTOM w0.114: R300.2 312.15,78.41 v4(311.61,78.41) U4.7
I2C_PCA9548_SD6_FRU_SDA: length 2.2
  TOP w0.114: R279.1 v2(311.35,34.52) U7.5
I2C_PCA9548_SD7_ADC128_R_SDA: length 3.2
  TOP w0.114: R150.1 304.79,31.5 v2(304.79,32.15) U2.19
I2C_PCA9548_SD7_ADC128_SCL: length 47.6
  TOP w0.114: R186.2 305.94,29.69 v2(306.2,29.95) 305.94,30.2 R151.2 ; R157.2 v2(267.18,29.08)
  BOTTOM w0.114: v2(267.18,29.08) 273.66,22.61 290.83,22.61 293.65,25.43 297.87,25.43 299.04,26.59 303.94,26.59 305.61,28.27 305.61,28.63 306.2,29.21 v2(306.2,29.95)
I2C_PCA9548_SD7_ADC128_SDA_R: length 2.2
  TOP w0.114: R158.1 265.24,28.45 U3.9
I2C_PE_SCL: length 34.7
  TOP w0.114: v2(308.92,26.19) 307.98,27.13 R86.1
  IN1 w0.147: v2(292.3,7.87) 292.3,8.03 292.76,8.48 292.76,8.64 293.98,9.86 296.72,9.86 303.1,16.23 303.1,19.76 306.27,22.94 306.27,24.38 308.08,26.19 v2(308.92,26.19)
  BOTTOM w0.114: J5.B5 291.83,5.94 291.54,6.22 291.54,7.11 v2(292.3,7.87)
I2C_PE_SCL_R: length 5.8
  TOP w0.114: U2.22 306.74,33.47 v2(306.96,33.25) 307.47,32.74 307.47,31.07 R87.2 R86.2
I2C_PE_SDA: length 34
  TOP w0.114: R85.1 v2(308.99,27.76)
  IN1 w0.147: v2(292.24,8.7) 293.76,10.21 296.47,10.21 302.74,16.48 302.74,19.91 305.92,23.08 305.92,24.53 308.99,27.6 v2(308.99,27.76)
  BOTTOM w0.114: v2(292.24,8.7) 290.83,7.28 J5.B6
I2C_PE_SDA_R: length 6
  TOP w0.114: R85.2 R88.2 308.48,31.07 308.48,32.49 v2(308.36,32.61) 307.39,33.58 U2.23
I2C_SLOT1_2N7002_G_SCL: length 2.7
  TOP w0.254: Q21.G 293.79,25.19 v2(294.45,24.52) R162.2
I2C_SLOT1_2N7002_G_SDA: length 2.7
  TOP w0.254: R192.2 288.86,25.02 288.37,25.02 288.11,24.77 v2(287.69,24.77) Q24.G
I2C_SLOT1_3V3_SCL: length 32.7
  TOP w0.114: Q21.S 294.72,27.75 294.93,27.96 R228.2 R203.2 296.24,28.19 v2(295.86,28.57)
  IN2 w0.147: v2(295.86,28.57) 296.41,29.12 296.41,29.93 296.24,30.1 293.21,30.1 293.07,30.25 293.07,30.67 293.21,30.82 296.46,30.82 296.6,30.97 296.6,31.2 296.46,31.35 294.99,31.35 294.84,31.5 294.84,31.86 294.99,32 296.66,32 296.81,32.15 296.81,39.63 295.64,40.8 292.46,40.8 291.75,40.08 291.75,37.84 J1.B5
I2C_SLOT1_3V3_SDA: length 30.8
  TOP w0.114: v2(290.15,28.68) R210.2 R233.2 288.62,27.96 288.41,27.75 Q24.S
  IN2 w0.147: J1.B6 290.83,40.43 291.54,41.15 295.78,41.15 297.16,39.78 297.16,32.38 297.89,31.65 297.89,28.96 296.8,27.86 291.21,27.86 290.4,28.68 v2(290.15,28.68)
I2C_SLOT2_2N7002_G_SCL: length 2.2
  TOP w0.254: Q15.G v2(295.61,65.85) 295.96,66.21 R107.2
I2C_SLOT2_2N7002_G_SDA: length 2.9
  TOP w0.254: Q18.G 290.4,65.81 v2(290.4,64.64) 290.17,64.41 288.97,64.41 R153.2
I2C_SLOT2_3V3_SCL: length 14.7
  TOP w0.114: Q15.S 294.42,68.6 R156.2 293.3,69.09 v2(293.27,69.06) 293.24,69.09 R226.2
  BOTTOM w0.114: v2(293.27,69.06) 292.76,69.06 292.03,69.8 292.03,72.05 291.89,72.18 291.54,72.18 291.4,72.32 291.4,72.51 291.54,72.64 291.89,72.64 292.03,72.77 292.03,74.35 291.05,75.32 291.05,77.61 J2.B5
I2C_SLOT2_3V3_SDA: length 14.7
  TOP w0.114: R227.2 v2(289.41,69.09) R159.2 290.13,68.6 290.36,68.37 Q18.S
  BOTTOM w0.114: v2(289.41,69.09) 289.97,69.65 289.97,74.6 290.61,75.24 290.61,80.18 J2.B6
NC_JTAG_TCK: length 0.6
  BOTTOM w0.114: U1.G11 v5(136.09,85.16)
NC_JTAG_TDI: length 0.6
  BOTTOM w0.114: U1.J6 v5(134.49,81.16)
NC_JTAG_TDO: length 0.6
  BOTTOM w0.114: U1.F11 v5(136.89,85.16)
NC_JTAG_TMS: length 0.6
  BOTTOM w0.114: U1.H11 v5(135.29,85.16)
NC_PEX_FATAL_ERR_N: length 0.6
  BOTTOM w0.114: U1.F14 v5(136.89,88.36)
NC_PEX_INTA_N: length 0.6
  BOTTOM w0.114: U1.B6 v5(139.29,81.16)
PCA9617_EN: length 3.9
  TOP w0.114: U12.5 104.07,44.16 v2(104.07,45.59)
  BOTTOM w0.114: R296.2 R211.1 104.34,45.31 v2(104.07,45.59)
PCIE_SLOT1_WAKE_N: length 4.9
  TOP w0.114: J1.B11 R5.2
PCIE_SLOT2_WAKE_N: length 4.8
  TOP w0.114: J2.B11 R6.2
PCIE_SLOT_PRES_N: length 98.2
  TOP w0.114: R132.2 R133.2 v2(276.68,13.21) R9.2 ; J5.A1 295.83,5.8 295.12,6.5 295.12,10.06 v2(296.5,11.43)
  IN1 w0.147: v2(276.68,13.21) 279.48,13.21 282.65,10.03 293.07,10.03 293.65,10.62 295.68,10.62 v2(296.5,11.43)
  IN2 w0.147: v2(215.24,9.88) 217.76,9.88 219.94,7.7 271.17,7.7 v2(276.68,13.21)
  BOTTOM w0.114: R134.2 214.88,10.24 v2(215.24,9.88)
PCIE_X1_SLOT_PRES_N: length 8.7
  TOP w0.114: v2(276.68,10.69) R9.1
  BOTTOM w0.114: v2(276.68,10.69) 278.13,9.25 278.13,5.94 277.83,5.64 J5.B17
PCIE_X4_SLOT_PRES_N: length 20.3
  TOP w0.114: R132.1 274.06,14.83 v2(273.86,14.63)
  IN2 w0.147: v2(273.86,14.63) 273.67,14.83 270.9,14.83 265.65,9.58 v2(263.78,9.58)
  BOTTOM w0.114: J5.B31 263.78,3.58 v2(263.78,9.58)
PCIE_X8_SLOT_PRES_N: length 41.9
  TOP w0.114: R133.1 276.46,14.83 275.77,15.52 v2(274.83,15.52)
  IN2 w0.147: v2(274.83,15.52) 270.23,15.52 264.92,10.21 246.99,10.21 v2(246,11.2)
  BOTTOM w0.114: v2(246,11.2) 247.14,10.06 247.14,6.07 246.83,5.75 J5.B48
PCIE_X16_SLOT_PRES_N: length 6.7
  BOTTOM w0.114: J5.B81 213.83,5.81 214.08,6.06 R134.1
PD_JTAG_TRST_N: length 4
  TOP w0.102: v5(136.09,78.76) 136.24,78.76 136.65,79.17 138.92,79.17 R10.1
  BOTTOM w0.114: U1.F3 136.49,79.16 v5(136.09,78.76)
PD_REXT_A0: length 25.8
  TOP w0.114: R11.1 v2(107.77,98.42)
  IN1 w0.102: 117.81,87.97 119.48,87.97 120.6,86.84 121.01,86.84 121.31,86.54 124.56,86.54 125.14,85.96 v5(125.69,85.96)
  IN1 w0.147: v2(107.77,98.42) 107.77,96.65 116.46,87.97 117.81,87.97
  BOTTOM w0.114: U1.W11 v5(125.69,85.96)
PD_REXT_A1: length 28.6
  TOP w0.114: v2(105.87,98.42) 105.23,99.06 105.23,99.84 R12.1
  IN1 w0.102: v5(124.89,85.16) 124.47,85.58 119.53,85.58 118.7,86.41 117.81,86.41
  IN1 w0.147: v2(105.87,98.42) 105.87,96.43 115.89,86.41 117.81,86.41
  BOTTOM w0.114: U1.Y11 v5(124.89,85.16)
PD_REXT_A2: length 20.9
  TOP w0.114: R13.1 123.01,104.92 123.01,101.85 v2(121.87,100.71)
  IN1 w0.102: v2(121.87,100.71) 121.59,100.43 121.59,90.2 123.04,88.75 124.61,88.75 124.89,88.47 v5(124.89,88.36)
  BOTTOM w0.114: U1.Y14 v5(124.89,88.36)
PD_REXT_A3: length 19.4
  TOP w0.114: v2(123.65,100.71) 123.65,100.97 124.16,101.47 124.16,104.92 R14.1
  IN1 w0.102: v2(123.65,100.71) 123.65,99.44 122.87,98.66 122.87,90.57 123.09,90.35 125.3,90.35 v5(125.69,89.96)
  BOTTOM w0.114: U1.W16 v5(125.69,89.96)
PD_REXT_A4: length 3.7
  TOP w0.114: v7(130.85,76.15) 130.75,76.24 R15.1
  BOTTOM w0.114: U1.N2 130.84,78.36 130.51,78.03 130.51,77.28 130.43,77.2 130.43,76.56 v7(130.85,76.15)
PD_REXT_A5: length 6.7
  TOP w0.102: v5(136.09,81.96) 136.09,81.92 136.48,81.53 136.48,80.9 136.6,80.77 139.02,80.77 v6(139.4,80.39) 140.01,79.78 R16.1
  BOTTOM w0.114: U1.G7 v5(136.09,81.96)
PD_REXT_A6: length 5.5
  TOP w0.102: v5(136.89,82.76) 137.29,82.36 139.43,82.36 140.9,80.89 R17.1
  BOTTOM w0.114: U1.F8 v5(136.89,82.76)
PD_REXT_A7: length 5
  TOP w0.102: v6(139.68,84.99) 139.52,84.84 139.02,84.84 138.92,84.74 137.27,84.74 v5(136.89,84.36)
  TOP w0.114: R18.1 140.15,84.52 v6(139.68,84.99)
  BOTTOM w0.114: U1.F10 v5(136.89,84.36)
PD_REXT_A8: length 1.7
  TOP w0.102: R19.1 128.85,94.72 v5(128.09,93.96)
  BOTTOM w0.114: U1.T21 v5(128.09,93.96)
PD_REXT_A9: length 1.5
  TOP w0.114: v5(132.89,94.76) 133.12,94.99 R20.1
  BOTTOM w0.114: U1.K22 v5(132.89,94.76)
PD_REXT_A10: length 7
  TOP w0.109: 140.58,90.3 139.95,89.66 139.95,88.79 v6(139.45,88.29) 139.09,88.29 138.76,87.96 136.49,87.96 v5(136.09,88.36)
  TOP w0.114: R23.1 140.77,90.49 140.58,90.3
  BOTTOM w0.114: U1.G14 v5(136.09,88.36)
PD_REXT_A11: length 8.1
  TOP w0.102: v5(136.09,87.56) 136.09,87.08 136.27,86.89 140.31,86.89 v6(140.62,87.2)
  TOP w0.109: 140.64,89.34 140.64,87.22 v6(140.62,87.2)
  TOP w0.114: R24.1 140.77,89.47 140.64,89.34
  BOTTOM w0.114: U1.G13 v5(136.09,87.56)
PD_REXT_B0: length 26.4
  TOP w0.114: v2(105.11,96.39) 104.73,96.77 R31.1
  IN1 w0.102: 117.81,86.02 118.52,85.31 121.59,85.31 122.13,84.76 124.49,84.76 v5(124.89,84.36)
  IN1 w0.147: 117.81,86.02 115.86,86.02 105.72,96.14 v2(105.11,96.39)
  BOTTOM w0.114: U1.Y10 v5(124.89,84.36)
PD_REXT_B1: length 32.3
  TOP w0.114: v2(104.09,97.79) 104.09,99.71 R32.1
  IN1 w0.102: 117.81,85.57 118.62,84.76 121.85,84.76 122.63,83.97 125.3,83.97 v5(125.69,84.36)
  IN1 w0.147: 117.81,85.57 115.17,85.57 104.09,96.65 v2(104.09,97.79)
  BOTTOM w0.114: U1.V10 126.49,84.36 v5(125.69,84.36)
PD_REXT_B2: length 20.7
  TOP w0.114: v2(109.81,96.52) R33.1
  IN1 w0.102: v5(124.89,87.56) 124.89,87.37 124.69,87.17 121.9,87.17 121.55,87.52 121.19,87.52 119.43,89.28 118.44,89.28 116.49,91.23
  IN1 w0.147: 116.49,91.23 111.2,96.52 v2(109.81,96.52)
  BOTTOM w0.114: U1.Y13 v5(124.89,87.56)
PD_REXT_B3: length 18.6
  TOP w0.114: v2(122.76,99.69) 122.76,100.84 123.65,101.73 R34.1
  IN1 w0.102: v5(125.69,88.36) 125.27,88.78 125.27,89.36 125.05,89.58 122.59,89.58 122,90.17 122,98.93 v2(122.76,99.69)
  BOTTOM w0.114: U1.W15 v5(125.69,88.36)
PD_REXT_B4: length 33.1
  TOP w0.114: R35.1 v2(102.44,98.93)
  IN1 w0.102: 117.81,84.56 118.29,84.07 121.41,84.07 122.33,83.16 125.12,83.16 125.3,82.98 125.3,82.45 125.69,82.06 v5(125.69,81.96)
  IN1 w0.147: v2(102.44,98.93) 102.95,98.42 102.95,96.22 114.62,84.55 117.81,84.56
  BOTTOM w0.114: U1.W7 v5(125.69,81.96)
PD_REXT_B5: length 5
  TOP w0.102: v5(132.89,81.16) 132.76,81.16 132.49,80.89 132.49,78.4 v6(132.62,78.28) 131.91,77.57 R36.1
  BOTTOM w0.114: U1.L6 v5(132.89,81.16)
PD_REXT_B6: length 6
  TOP w0.102: R37.1 140.08,82.17 139.07,83.18 136.47,83.18 136.09,82.8 v5(136.09,82.76)
  BOTTOM w0.114: U1.G8 v5(136.09,82.76)
PD_REXT_B7: length 6.1
  TOP w0.109: v6(139.9,83.16) 139.9,83.49 139.45,83.94 136.73,83.94 136.73,83.94 136.5,83.94 v5(136.09,84.36)
  TOP w0.114: v6(139.9,83.16) 140.23,83.16 140.27,83.12 R38.1
  BOTTOM w0.114: U1.G10 v5(136.09,84.36)
PD_REXT_B8: length 1.4
  TOP w0.102: v5(128.09,94.76) 127.27,94.76 R39.1
  BOTTOM w0.114: U1.T22 v5(128.09,94.76)
PD_REXT_B9: length 8.5
  TOP w0.102: v5(136.89,90.76) 136.89,90.8 137.24,91.15 137.9,91.15 138.08,91.33 138.08,94.13 138.3,94.36 138.97,94.36 139.16,94.17 v6(139.75,94.17)
  TOP w0.114: R40.1 v6(139.75,94.17)
  BOTTOM w0.114: U1.G17 136.09,90.76 v5(136.89,90.76)
PD_REXT_B10: length 6.9
  TOP w0.102: v5(136.09,89.16) 136.29,89.16 136.68,89.55 138.72,89.55 138.89,89.73 138.89,90.57 139.03,90.7 v6(139.47,90.7)
  TOP w0.114: v6(139.47,90.7) 139.62,90.7 140.78,91.86 R41.1
  BOTTOM w0.114: v5(136.09,89.16) 135.69,89.56 U1.G16
PD_REXT_B11: length 7.9
  TOP w0.109: v7(141.43,86.77) 141.68,86.77 141.77,86.69 142.57,86.69 R42.1
  BOTTOM w0.114: U1.H13 134.9,87.16 135.29,86.77 v7(141.43,86.77)
PD_REXT_CMU: length 28
  TOP w0.114: R43.1 106.76,97.28 v2(107.14,96.9)
  IN1 w0.102: v5(125.69,85.16) 125.43,85.16 124.25,86.34 121.52,86.34 120.96,85.78 119.81,85.78 118.65,86.94 117.81,86.94
  IN1 w0.147: v2(107.14,96.9) 107.14,95.59 115.78,86.94 117.81,86.94
  BOTTOM w0.114: U1.W10 v5(125.69,85.16)
PD_SLOT1_A1: length 12
  TOP w0.114: v2(289.89,42.55) 289.24,42.55 R200.1
  BOTTOM w0.114: J1.A1 295.79,35.25 295.05,35.99 295.05,38.02 293.96,39.12 293.96,40.89 293.19,41.66 290.78,41.66 v2(289.89,42.55)
PD_SLOT2_A1: length 12
  TOP w0.114: v2(290.53,83.19) 288.9,83.19 R199.1
  BOTTOM w0.114: v2(290.53,83.19) 291.67,82.04 292.69,82.04 294.05,80.68 294.05,80.07 294.84,79.27 294.84,76.45 295.4,75.89 J2.A1
PD_VOE_N: length 15.9
  TOP w0.114: R76.2 305.1,62.47 v2(305.41,62.15) ; 299.71,61.07 U9.28 299.71,61.87 v2(299.54,62.04) ; 302.11,61.07 U9.22 302.11,62.05 v2(302.11,62.05) ; 303.09,57.7 U9.13 304.1,57.7 v2(304.2,57.61)
  IN1 w0.147: v2(299.54,62.04) 302.1,62.04 v2(302.11,62.05) 302.39,62.33 305.23,62.33 v2(305.41,62.15) 303.51,60.25 303.51,58.29 v2(304.2,57.61)
PE_CPU_RX_C_DN<0>: length 179.3
  TOP w0.089: 122.51,75.31 122.51,75.34 122.57,75.39 122.57,75.85 123.53,76.81 123.53,77.04 123.41,77.16 v5(123.29,77.16)
  TOP w0.135: 122.51,75.31 122.52,75.31 122.52,72.35 v8(126.61,68.26) 130.1,64.77 132.74,64.77 176.91,56.98 206.49,36.26 207.28,35.13 212.14,31.73 268.51,21.79 269.29,21.24 269.33,21.05 269.77,20.74 269.96,20.77 276.95,15.88 278.18,14.07 278.18,12.7 C35.1
  BOTTOM w0.135: U1.AB1 v5(123.29,77.16)
PE_CPU_RX_C_DN<1>: length 179.6
  TOP w0.089: v5(123.29,77.96) 123.29,77.81 123.22,77.74 121.9,77.74 121.5,78.14 120.94,78.14 120.52,77.72 120.52,77.31 120.43,77.22 120.42,77.22 120.41,77.21 120.41,77.2
  TOP w0.135: C36.1 273.18,12.7 273.18,13.23 272.03,14.38 271.51,14.74 270.24,15.63 270.05,15.6 269.45,16.02 269.41,16.21 268.97,16.52 268.79,16.49 268.18,16.92 268.15,17.1 267.7,17.41 267.52,17.37 266.91,17.8 266.88,17.99 266.34,18.36 266.21,18.34 265.69,18.7 265.66,18.84 265.22,19.15 265.02,19.11 264.58,19.42 264.55,19.62 261.49,21.76 211.72,30.54 206.17,34.42 205.44,35.48 176.33,55.86 134.32,63.27 129.82,63.27 v8(123.43,69.66) 121.3,71.8 121.3,74.58 120.41,75.47 120.41,77.2
  BOTTOM w0.135: U1.AB2 v5(123.29,77.96)
PE_CPU_RX_C_DN<2>: length 179.2
  TOP w0.089: 120.09,78.87 120.18,78.96 120.18,78.96 120.59,79.36 123.09,79.36 v5(123.29,79.56)
  TOP w0.135: C37.1 269.17,12.69 269.17,13.56 269.14,13.75 268.96,14 268.75,14.04 268.47,14.45 268.5,14.66 268.25,15.03 267.16,15.79 266.95,15.75 266.51,16.06 266.48,16.27 266.04,16.57 265.83,16.54 265.39,16.85 265.36,17.05 264.92,17.36 264.71,17.32 264.27,17.63 264.24,17.84 263.79,18.15 263.57,18.11 263.15,18.4 263.11,18.62 262.33,19.17 257.3,21.25 257.3,21.25 257.18,21.3 211.02,29.44 205.13,33.56 204.55,34.39 175.52,54.69 135.07,61.82 129.55,61.82 v8(125.35,66.02) 119.69,71.68 119.69,74.78 119.38,75.08 119.38,78.16 120.09,78.87
  BOTTOM w0.135: U1.AB4 v5(123.29,79.56)
PE_CPU_RX_C_DN<3>: length 178.5
  TOP w0.089: 120.98,80.26 121.08,80.17 123.1,80.17 v5(123.29,80.36)
  TOP w0.135: C38.1 265.15,12.67 265.15,13.57 265.13,13.61 264.53,14.02 263.82,14.52 263.68,14.5 263.17,14.85 263.14,15 262.7,15.31 262.53,15.28 262.05,15.62 262.02,15.79 261.58,16.09 261.39,16.06 260.93,16.38 260.9,16.57 260.45,16.88 260.24,16.84 259.81,17.14 259.77,17.36 259.33,17.67 259.13,17.63 258.68,17.94 258.65,18.14 258.21,18.45 258.21,18.45 255.46,20.38 210.55,28.3 210.51,28.33 204.27,32.7 203.88,33.25 174.78,53.6 136.07,60.43 129.09,60.43 v8(123.05,66.47) 121.82,67.7 118.33,71.19 118.33,78.58 120.02,80.26 120.98,80.26
  BOTTOM w0.135: U1.AB5 v5(123.29,80.36)
PE_CPU_RX_C_DN<4>: length 177.7
  TOP w0.089: v5(123.29,81.96) 123.1,81.77 121.47,81.77 121.04,82.2 120.38,82.2 120.32,82.26 120.3,82.26
  TOP w0.135: 120.3,82.26 120.14,82.26 119.5,82.15 118.16,81.21 117.13,79.76 117.13,77.46 116.99,77.32 116.99,76.68 117.13,76.55 117.13,70.51 v8(125.11,62.53) 128.53,59.11 136.62,59.11 173.8,52.55 210.08,27.16 247.83,20.5 251.69,18.9 251.73,18.79 252.38,18.52 252.49,18.57 252.99,18.36 253.04,18.25 253.68,17.98 253.79,18.03 254.29,17.82 254.35,17.68 254.96,17.43 255.1,17.49 255.5,17.33 256.04,16.94 256.07,16.81 256.59,16.45 256.72,16.47 258.05,15.54 258.33,15.14 258.29,14.92 258.6,14.48 258.82,14.44 259.16,13.96 259.16,13.64 259.03,13.51 259.03,13.08 259.16,12.95 259.16,12.68 C91.1
  BOTTOM w0.135: U1.AB7 v5(123.29,81.96)
PE_CPU_RX_C_DN<5>: length 177.7
  TOP w0.089: v5(123.29,82.76) 123.1,82.57 121.84,82.57 121.43,82.98 119.79,82.98 119.74,83.04 119.72,83.04
  TOP w0.135: C92.1 255.17,12.69 255.17,13.18 255.04,13.3 255.04,13.89 255.17,14.02 255.17,14.61 254.46,15.32 253.98,15.65 253.82,15.62 253.3,15.99 253.27,16.15 252.83,16.46 252.67,16.43 252.15,16.8 252.12,16.96 251.68,17.26 251.5,17.23 251,17.58 250.97,17.76 250.48,18.1 250.21,18.21 250.05,18.15 249.46,18.39 249.39,18.55 248.94,18.74 248.78,18.67 248.22,18.9 248.15,19.07 247.5,19.34 209.61,26.02 173.33,51.42 137.13,57.8 127.9,57.8 v8(121.54,64.16) 115.93,69.77 115.93,79.91 116,80.31 116.49,81.02 117.31,82.19 118.35,82.92 119.03,83.04 119.04,83.04 119.72,83.04
  BOTTOM w0.135: U1.AB8 v5(123.29,82.76)
PE_CPU_RX_C_DN<6>: length 177.6
  TOP w0.089: 119.36,84.27 119.38,84.27 119.44,84.21 121.23,84.21 121.44,84.01 121.84,84.01 121.96,84.13 123.2,84.13 123.29,84.22 v5(123.29,84.36)
  TOP w0.135: 119.36,84.27 118.49,84.27 118.1,84.2 116.49,83.08 116.43,83.04 115.25,81.34 114.73,80.6 114.73,69.06 122.01,61.77 v8(123.59,60.19) 127.21,56.58 137.13,56.58 172.79,50.29 209.02,24.9 247.13,18.18 247.82,17.7 247.86,17.47 248.3,17.16 248.53,17.2 248.97,16.9 249.01,16.67 249.45,16.36 249.68,16.4 250.3,15.96 250.79,15.27 250.92,14.56 250.8,14.39 250.9,13.85 251.06,13.73 251.22,12.82 251.22,12.74 C93.1
  BOTTOM w0.135: U1.AB10 v5(123.29,84.36)
PE_CPU_RX_C_DN<7>: length 177.4
  TOP w0.089: 118.88,85.44 118.9,85.44 118.96,85.38 120.12,85.38 120.57,84.94 121.89,84.94 121.97,85.01 122.43,85.01 122.51,84.94 123.17,84.94 123.29,85.05 v5(123.29,85.16)
  TOP w0.135: C94.1 247.17,12.69 247.17,13 247.04,13.13 247.04,13.56 247.17,13.69 247.17,14.09 246.82,14.59 246.61,14.74 246.38,14.7 246.1,14.89 246.06,15.12 245.62,15.43 245.4,15.39 244.94,15.71 244.9,15.94 244.37,16.31 243.73,16.57 243.54,16.5 243,16.72 242.92,16.91 239.6,18.29 208.55,23.76 172.33,49.11 137.66,55.23 126.5,55.23 v8(120.55,61.18) 113.53,68.2 113.53,81.24 113.6,81.64 115.28,84.04 116.49,84.89 117.13,85.34 117.7,85.44 117.7,85.44 118.88,85.44
  BOTTOM w0.135: U1.AB11 v5(123.29,85.16)
PE_CPU_RX_C_DN<8>: length 176.7
  TOP w0.089: 118.42,86.64 118.44,86.64 118.5,86.58 118.8,86.58 119.35,87.13 122.86,87.13 v5(123.29,87.56)
  TOP w0.135: C95.1 242.17,12.68 242.17,12.98 242.01,13.13 242.01,13.56 242.17,13.72 242.17,14.09 241.99,14.6 241.78,14.75 241.61,14.71 241.17,15.02 241.14,15.19 240.7,15.5 240.52,15.47 240,15.83 239.97,16.01 239.43,16.4 239.18,16.5 239,16.42 238.46,16.65 238.38,16.83 237.89,17.03 237.7,16.96 237.17,17.18 237.09,17.36 236.47,17.62 208.08,22.62 171.86,47.98 138.29,53.9 125.68,53.9 v8(121.99,57.59) 115.1,64.48 115.1,64.88 112.33,67.65 112.33,81.95 114.48,85.02 116.46,86.41 116.49,86.42 117.02,86.64 118.42,86.64
  BOTTOM w0.135: U1.AB13 v5(123.29,87.56)
PE_CPU_RX_C_DN<9>: length 176.7
  TOP w0.089: 118.93,87.99 118.95,87.99 119.03,87.91 121.97,87.91 122.21,88.15 123.08,88.15 v5(123.29,88.36)
  TOP w0.135: C96.1 237.82,12.34 238.18,12.69 238.18,12.93 238.05,13.06 238.05,13.51 238.18,13.64 238.18,14.05 237.9,14.44 237.66,14.48 237.35,14.92 237.39,15.17 237.11,15.58 235.76,16.52 234.91,16.67 234.77,16.57 234.18,16.67 234.08,16.82 233.55,16.91 233.42,16.83 232.8,16.94 232.71,17.06 232.18,17.15 232.02,17.04 231.46,17.14 231.34,17.3 207.49,21.51 171.28,46.86 155.35,49.67 139.41,52.48 125.17,52.48 v8(119.76,57.89) 113.28,64.37 113.28,65 111.12,67.16 111.12,82.57 111.21,83.07 112.26,84.58 113.72,86.03 116.19,87.76 116.49,87.82 117.47,87.99 117.49,87.99 118.93,87.99
  BOTTOM w0.135: U1.AB14 v5(123.29,88.36)
PE_CPU_RX_C_DN<10>: length 180
  TOP w0.089: 118.8,89.2 118.82,89.2 118.88,89.14 119.35,89.14 119.61,89.4 122.54,89.4 122.9,89.75 123.08,89.75 v5(123.29,89.96)
  TOP w0.135: 118.8,89.2 116.85,89.2 116.49,89.14 115.83,89.02 112.75,86.86 110.85,84.97 110.46,84.41 109.92,83.11 109.92,66.66 111.89,64.69 111.89,63.5 v8(120.73,54.66) 124.31,51.08 140.41,51.08 170.6,45.76 173.54,43.7 173.67,42.95 174.11,42.64 174.86,42.78 175.09,42.61 175.22,41.86 175.66,41.56 176.41,41.69 176.64,41.53 176.77,40.78 177.21,40.47 177.96,40.6 178.19,40.44 178.33,39.69 178.77,39.38 179.51,39.51 179.75,39.35 179.88,38.6 180.32,38.29 181.07,38.43 181.97,37.79 182.07,37.2 182.87,36.65 183.46,36.75 184.05,36.34 184.15,35.75 184.95,35.19 185.54,35.3 206.81,20.4 227.29,16.79 227.41,16.61 227.94,16.52 228.12,16.65 228.65,16.55 228.78,16.37 229.31,16.28 229.49,16.4 230.57,16.21 231.1,15.84 231.79,15.72 231.9,15.56 232.44,15.47 232.59,15.58 233.17,15.48 233.67,15.13 233.74,15.03 233.69,14.79 233.82,14.61 234.03,14.58 234.16,14.42 234.16,14.04 234.01,13.89 234.01,13.35 234.16,13.2 234.16,12.68 C97.1
  BOTTOM w0.124: U1.AB16 v5(123.29,89.96)
PE_CPU_RX_C_DN<11>: length 182.3
  TOP w0.089: v5(123.29,90.76) 123.08,90.55 122.81,90.55 122.45,90.2 119.95,90.2 119.54,90.61 118.93,90.61 118.87,90.67
  TOP w0.135: C98.1 230.2,12.72 230.2,13.12 230.05,13.27 230.05,13.81 230.2,13.96 230.2,14.55 229.77,14.99 229.16,14.99 229.03,14.86 228.29,14.86 228.16,14.99 227.53,14.99 227.39,15.09 227.23,15.06 226.84,15.32 226.82,15.49 226.55,15.67 225.77,15.81 225.58,15.68 225.06,15.77 224.92,15.96 224.11,16.11 223.95,16 223.4,16.09 223.28,16.25 204.93,19.52 203.02,20.85 201.84,21.68 201.84,21.68 200.66,22.5 200.41,22.46 199.97,22.77 199.92,23.02 169.11,44.6 140.26,49.68 123.44,49.68 v8(119.25,53.87) 114.53,58.6 112.67,58.93 112.67,58.93 108.53,59.66 106.72,60.92 105.97,61.99 105.92,62.28 105.92,65.49 107.75,68.09 108.32,71.34 108.32,83.16 109.42,85.17 109.43,85.18 110.67,86.96 114.31,89.5 114.34,89.71 114.75,89.99 114.95,89.96 115.81,90.56 116.44,90.67 116.47,90.67 118.87,90.67 118.87,90.67
  BOTTOM w0.124: U1.AB17 v5(123.29,90.76)
